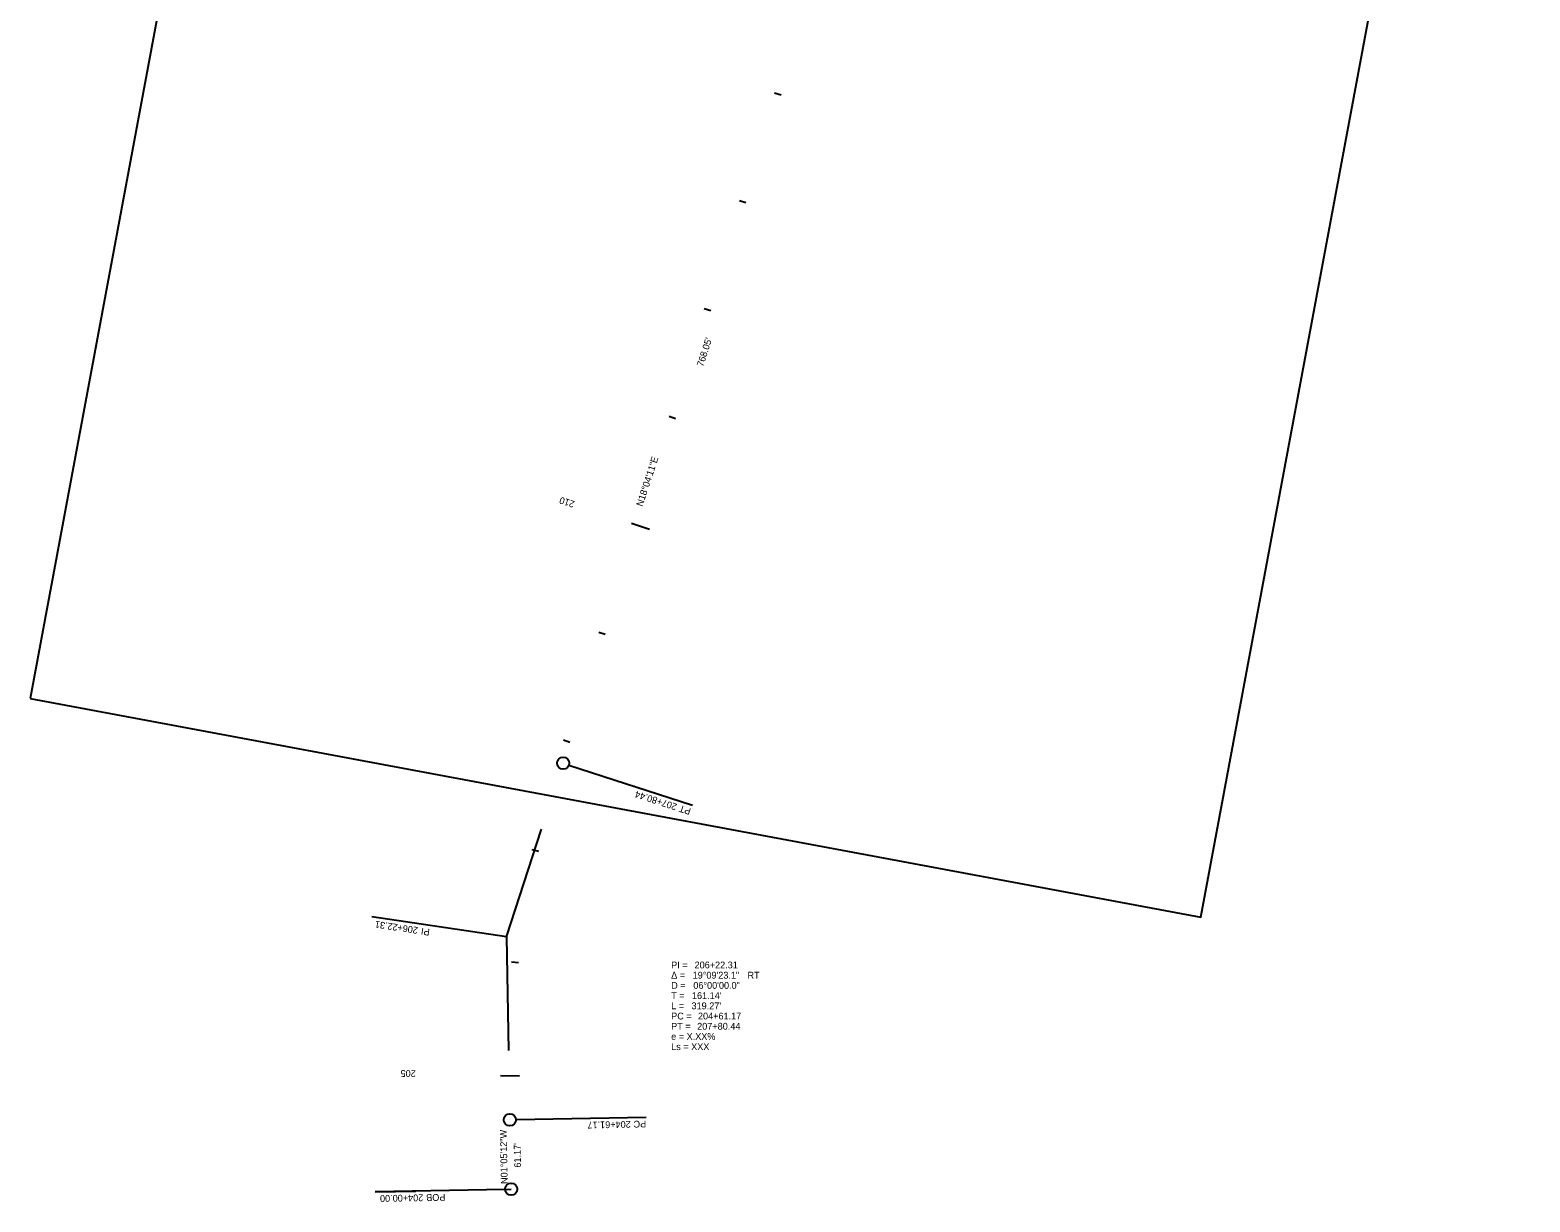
# Model space of a CAD drawing. Extents: x 1802364 to 1804577, y 572742 to 575010.
# Drawn here: x 1802779 to 1804101, y 572742 to 573774 of the extents above; entities that cross this region are included whole.
import ezdxf

# ---------------------------------------------------------------- set-up
doc = ezdxf.new("R2010")
doc.units = 0
for name, color, linetype in [('_CIVIL_CONSTRUCTION', 7, 'Continuous'), ('MOD_COR_TemplateDrop', 7, 'Continuous'), ('MOD_Points', 7, 'Continuous')]:
    doc.layers.add(name, color=color, linetype=linetype)

msp = doc.modelspace()

# ---------------------------------------------------------------- linework, layer by layer
at = {"layer": '_CIVIL_CONSTRUCTION'}
for p, q in [((1803435.4, 573719.1), (1803441.1, 573717.3)), ((1803404.4, 573624.1), (1803410.1, 573622.2)), ((1803373.4, 573529), (1803379.1, 573527.1)), ((1803342.4, 573433.9), (1803348.1, 573432.1)), ((1803309.1, 573339.6), (1803325, 573334.4)), ((1803280.3, 573243.8), (1803286, 573241.9)), ((1803249.3, 573148.7), (1803255, 573146.9)), ((1803249, 573128.3), (1803249, 573128.3)), ((1803254, 573126.6), (1803363, 573091.1)), ((1803363, 573091.1), (1803363, 573091.1)), ((1803199, 572975.1), (1803230, 573070.2)), ((1803221.4, 573052.2), (1803227.3, 573050.8)), ((1803199, 572975.1), (1803080.3, 572992.8)), ((1803080.3, 572992.8), (1803080.3, 572992.8)), ((1803199, 572975.1), (1803200.9, 572875.1)), ((1803203.5, 572953.2), (1803209.5, 572952.5)), ((1803193.7, 572853), (1803210.5, 572852.6)), ((1803202, 572814), (1803202, 572814)), ((1803207.4, 572814.1), (1803322, 572816.3)), ((1803322, 572816.3), (1803322, 572816.3)), ((1803197.9, 572752.7), (1803083.2, 572750.5)), ((1803083.2, 572750.5), (1803119.2, 572751.2)), ((1803197.2, 572752.7), (1803203.2, 572752.8)), ((1803203.2, 572752.8), (1803203.2, 572752.8))]:
    msp.add_line(p, q, dxfattribs=at)
for centre in [(1803249, 573128.3), (1803202, 572814), (1803203.2, 572752.8)]:
    msp.add_circle(centre, 5.34, dxfattribs=at)
at = {"layer": 'MOD_COR_TemplateDrop'}
msp.add_lwpolyline([(1802779, 573185.2), (1803811.2, 572992.6), (1804101.3, 574547.6), (1803069.1, 574740.2)], close=True, dxfattribs=at)

# ---------------------------------------------------------------- texts
at = {"layer": '_CIVIL_CONSTRUCTION'}
for s, rotation, p in [('N18°04\'11"E', 71.9303, (1803318.9, 573354)), ('210', 161.9303, (1803259.6, 573358.9)), ('207+80.44', 161.9303, (1803349.8, 573092.2)), ('PT', 161.9303, (1803362.1, 573088.2)), ('206+22.31', 171.5085, (1803121.3, 572983.7)), ('PI ', 171.5085, (1803131.7, 572982.1)), ('205', 178.757, (1803119.1, 572857.6)), ('204+61.17', 181.0867, (1803308.5, 572813)), ('PC', 181.0867, (1803322.1, 572813.3)), ('N01°05\'12"W', 91.0867, (1803200.1, 572757.5)), ('204+00.00', 181.0867, (1803125.6, 572748.3)), ('POB ', 181.0867, (1803145.1, 572748.7))]:
    msp.add_text(s, height=6, rotation=rotation, dxfattribs=at).set_placement(p)
for s, p in [('Δ = ', (1803344.2, 572938.4)), ('PI = ', (1803344.2, 572947.4)), ('19°09\'23.1"', (1803363.1, 572938.4)), ('206+22.31', (1803364.8, 572947.4)), (' RT', (1803409.3, 572938.4)), ('D = ', (1803344.2, 572929.4)), ('06°00\'00.0"', (1803363.7, 572929.4)), ('T = ', (1803344.2, 572920.4)), ('L = ', (1803344.2, 572911.4)), ("319.27'", (1803362.1, 572911.4)), ("161.14'", (1803362.5, 572920.4)), ('PC = ', (1803344.2, 572902.4)), ('204+61.17', (1803367.8, 572902.4)), ('e = X.XX%', (1803344.2, 572884.4)), ('PT = ', (1803344.2, 572893.4)), ('207+80.44', (1803367.1, 572893.4)), ('Ls = XXX', (1803344.2, 572875.4))]:
    msp.add_text(s, height=6, dxfattribs=at).set_placement(p)
at = {"layer": 'MOD_Points'}
for s, rotation, p in [("768.05'", 71.9303, (1803372.3, 573477.2)), ("61.17'", 91.0867, (1803211.8, 572771.9))]:
    msp.add_text(s, height=6, rotation=rotation, dxfattribs=at).set_placement(p)

doc.saveas('drawing.dxf')
